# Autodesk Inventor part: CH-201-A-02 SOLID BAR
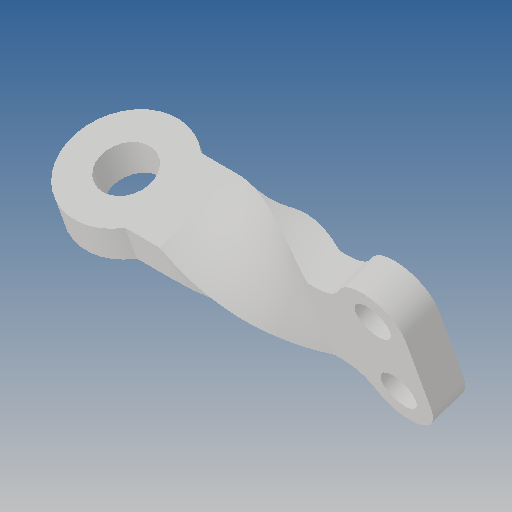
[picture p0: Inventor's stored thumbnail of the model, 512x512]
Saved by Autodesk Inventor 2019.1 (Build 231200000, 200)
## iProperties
Created: 2012-09
Part Number: CH-201-A-02 SOLID BAR
Material: Ogólny
Document SubType Name: Modeling
Designer: CADENGINEERING4
Density: 1 g/cm^3
Appearance: Domyślna
Author: CADENGINEERING4
Revision Number: ÈÎºÎ
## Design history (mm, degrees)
feature "À­Éì2"
node "Bryła1"
